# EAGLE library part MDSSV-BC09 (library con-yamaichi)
YAMAICHI CONNECTOR
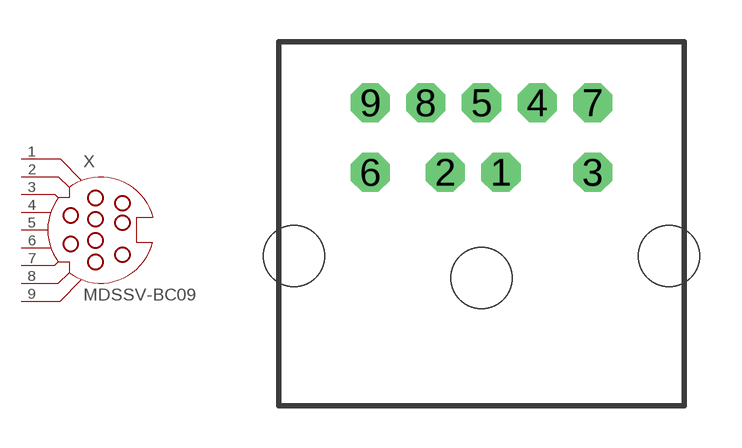
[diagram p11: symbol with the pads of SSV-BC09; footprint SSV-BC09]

Designator prefix X

## MDSSV-BC09 (OC_FARNELL: unknown; OC_NEWARK: unknown)  [SSV-BC09]
1  1  pas
2  2  pas
3  3  pas
4  4  pas
5  5  pas
6  6  pas
7  7  pas
8  8  pas
9  9  pas

## Footprint SSV-BC09 (pad centres in mm)
Mini Din YAMAICHI CONNECTOR
drill 0.9 octagon: 1 0.7,8.5; 2 -1.3,8.5; 3 4,8.5; 4 2,11; 5 0,11; 6 -4,8.5; 7 4,11; 8 -2,11; 9 -4,11
hole 2.2 at -6.75,5.5
hole 2.2 at 0,4.7
hole 2.2 at 6.75,5.5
